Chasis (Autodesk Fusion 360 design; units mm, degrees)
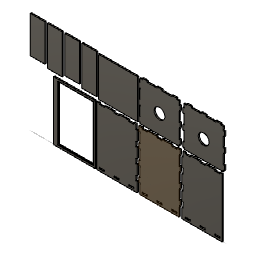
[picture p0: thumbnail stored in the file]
sketch "Sketch1" plane through (0, 0, 0) normal (0, 0, 1) x axis (1, 0, 0)
  line L1 (70, 421.7517) -> (-330, 421.7517)
  line L2 (508.2728, 1021.7517) -> (96.2728, 1021.7517)
  line L3 (508.2728, 421.7517) -> (508.2728, 1021.7517)
  line L4 (96.2728, 421.7517) -> (508.2728, 421.7517)
  line L5 (70, 971.7517) -> (82, 971.7517)
  line L6 (82, 871.7517) -> (70, 871.7517)
  line L7 (70, 821.7517) -> (82, 821.7517)
  line L8 (82, 721.7517) -> (70, 721.7517)
  line L9 (70, 671.7517) -> (82, 671.7517)
  line L10 (82, 571.7517) -> (70, 571.7517)
  line L11 (70, 521.7517) -> (82, 521.7517)
  line L12 (96.2728, 1021.7517) -> (108.2728, 1021.7517)
  line L13 (96.2728, 971.7517) -> (96.2728, 1021.7517)
  line L14 (108.2728, 971.7517) -> (96.2728, 971.7517)
  line L15 (108.2728, 1021.7517) -> (108.2728, 971.7517)
  line L16 (108.2728, 871.7517) -> (108.2728, 821.7517)
  line L17 (108.2728, 821.7517) -> (96.2728, 821.7517)
  line L18 (96.2728, 871.7517) -> (108.2728, 871.7517)
  line L19 (108.2728, 721.7517) -> (108.2728, 671.7517)
  line L20 (108.2728, 671.7517) -> (96.2728, 671.7517)
  line L21 (96.2728, 721.7517) -> (108.2728, 721.7517)
  line L22 (108.2728, 571.7517) -> (108.2728, 521.7517)
  line L23 (108.2728, 521.7517) -> (96.2728, 521.7517)
  line L24 (96.2728, 571.7517) -> (108.2728, 571.7517)
  line L25 (-342, 821.7517) -> (-330, 821.7517)
  line L26 (-342, 521.7517) -> (-330, 521.7517)
  line L27 (-330, 571.7517) -> (-342, 571.7517)
  line L28 (-342, 671.7517) -> (-330, 671.7517)
  line L29 (-330, 721.7517) -> (-342, 721.7517)
  line L30 (-330, 871.7517) -> (-342, 871.7517)
  line L31 (-330, 871.7517) -> (-330, 971.7517)
  line L32 (-330, 721.7517) -> (-330, 821.7517)
  line L33 (-330, 571.7517) -> (-330, 671.7517)
  line L34 (-330, 421.7517) -> (-330, 521.7517)
  line L35 (70, 521.7517) -> (70, 421.7517)
  line L36 (70, 671.7517) -> (70, 571.7517)
  line L37 (70, 821.7517) -> (70, 721.7517)
  line L38 (70, 971.7517) -> (70, 871.7517)
  line L39 (96.2728, 1021.7517) -> (96.2728, 421.7517)
  line L40 (-155, 441.7517) -> (-105, 441.7517)
  line L41 (-155, 453.7517) -> (-155, 441.7517)
  line L42 (-105, 453.7517) -> (-155, 453.7517)
  line L43 (-105, 441.7517) -> (-105, 453.7517)
  line L44 (45, 441.7517) -> (45, 453.7517)
  line L45 (-5, 441.7517) -> (45, 441.7517)
  line L46 (45, 453.7517) -> (-5, 453.7517)
  line L47 (-5, 453.7517) -> (-5, 441.7517)
  line L48 (-255, 441.7517) -> (-255, 453.7517)
  line L49 (-305, 441.7517) -> (-255, 441.7517)
  line L50 (-255, 453.7517) -> (-305, 453.7517)
  line L51 (-305, 453.7517) -> (-305, 441.7517)
  line L52 (283.2728, 453.7517) -> (283.2728, 441.7517)
  line L53 (333.2728, 453.7517) -> (283.2728, 453.7517)
  line L54 (333.2728, 441.7517) -> (333.2728, 453.7517)
  line L55 (333.2728, 441.7517) -> (283.2728, 441.7517)
  line L56 (483.2728, 453.7517) -> (433.2728, 453.7517)
  line L57 (433.2728, 453.7517) -> (433.2728, 441.7517)
  line L58 (483.2728, 441.7517) -> (433.2728, 441.7517)
  line L59 (483.2728, 441.7517) -> (483.2728, 453.7517)
  line L60 (183.2728, 453.7517) -> (133.2728, 453.7517)
  line L61 (133.2728, 453.7517) -> (133.2728, 441.7517)
  line L62 (183.2728, 441.7517) -> (133.2728, 441.7517)
  line L63 (183.2728, 441.7517) -> (183.2728, 453.7517)
  line L64 (-342, 971.7517) -> (-330, 971.7517)
  line L65 (82, 1021.7517) -> (-342, 1021.7517)
  line L66 (-255, 1021.7517) -> (-305, 1021.7517)
  line L67 (-255, 1009.7517) -> (-255, 1021.7517)
  line L68 (-305, 1009.7517) -> (-255, 1009.7517)
  line L69 (-305, 1021.7517) -> (-305, 1009.7517)
  line L70 (-105, 1021.7517) -> (-155, 1021.7517)
  line L71 (-105, 1009.7517) -> (-105, 1021.7517)
  line L72 (-155, 1009.7517) -> (-105, 1009.7517)
  line L73 (-155, 1021.7517) -> (-155, 1009.7517)
  line L74 (45, 1021.7517) -> (-5, 1021.7517)
  line L75 (45, 1009.7517) -> (45, 1021.7517)
  line L76 (-5, 1009.7517) -> (45, 1009.7517)
  line L77 (-5, 1021.7517) -> (-5, 1009.7517)
  line L78 (183.2728, 1021.7517) -> (133.2728, 1021.7517)
  line L79 (183.2728, 1009.7517) -> (183.2728, 1021.7517)
  line L80 (133.2728, 1009.7517) -> (183.2728, 1009.7517)
  line L81 (133.2728, 1021.7517) -> (133.2728, 1009.7517)
  line L82 (333.2728, 1021.7517) -> (283.2728, 1021.7517)
  line L83 (333.2728, 1009.7517) -> (333.2728, 1021.7517)
  line L84 (283.2728, 1009.7517) -> (333.2728, 1009.7517)
  line L85 (283.2728, 1021.7517) -> (283.2728, 1009.7517)
  line L86 (483.2728, 1021.7517) -> (433.2728, 1021.7517)
  line L87 (483.2728, 1009.7517) -> (483.2728, 1021.7517)
  line L88 (433.2728, 1009.7517) -> (483.2728, 1009.7517)
  line L89 (433.2728, 1021.7517) -> (433.2728, 1009.7517)
  line L90 (-353.2483, 1448.6304) -> (-751.2483, 1448.6304)
  line L91 (-353.2483, 1050.6304) -> (-353.2483, 1448.6304)
  line L92 (-751.2483, 1050.6304) -> (-353.2483, 1050.6304)
  line L93 (-751.2483, 1448.6304) -> (-751.2483, 1050.6304)
  line L94 (1883.2395, 210.7799) -> (1883.2395, -189.2201)
  line L95 (2283.2395, -189.2201) -> (2283.2395, 210.7799)
  line L96 (2283.2395, 210.7799) -> (1883.2395, 210.7799)
  line L97 (1883.2395, -189.2201) -> (2283.2395, -189.2201)
  line L98 (-342, 521.7517) -> (-342, 571.7517)
  line L99 (-342, 671.7517) -> (-342, 721.7517)
  line L100 (-342, 971.7517) -> (-342, 1021.7517)
  line L101 (-342, 821.7517) -> (-342, 871.7517)
  line L102 (82, 521.7517) -> (82, 571.7517)
  line L103 (82, 671.7517) -> (82, 721.7517)
  line L104 (82, 971.7517) -> (82, 1021.7517)
  line L105 (82, 821.7517) -> (82, 871.7517)
  line L106 (-305, 1459) -> (-255, 1459)
  line L107 (70, 1060) -> (82, 1060)
  line L108 (70, 1260) -> (70, 1360)
  line L109 (82, 1210) -> (82, 1260)
  line L110 (70, 1110) -> (70, 1210)
  line L111 (-330, 1210) -> (-342, 1210)
  line L112 (82, 1060) -> (82, 1110)
  line L113 (-330, 1210) -> (-330, 1110)
  line L114 (82, 1110) -> (70, 1110)
  line L115 (-330, 1060) -> (-342, 1060)
  line L116 (-330, 1360) -> (-330, 1260)
  line L117 (-342, 1210) -> (-342, 1260)
  line L118 (-330, 1060) -> (-330, 1047)
  line L119 (70, 1047) -> (70, 1060)
  line L120 (-330, 1047) -> (70, 1047)
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  point P55 (-305, 1021.7517)
  point P59 (-155, 1021.7517)
  point P63 (-5, 1021.7517)
  point P67 (133.2728, 1021.7517)
  point P71 (283.2728, 1021.7517)
  point P75 (433.2728, 1021.7517)
  point P39 (-305, 453.7517)
  point P79 (-305, 453.7517)
  point P24 (-330, 521.7517)
  point P80 (-330, 521.7517)
  point P23 (-330, 571.7517)
  point P81 (-330, 571.7517)
  point P26 (-330, 671.7517)
  point P82 (-330, 671.7517)
  point P42 (-255, 453.7517)
  point P83 (-255, 453.7517)
  point P41 (-305, 441.7517)
  point P84 (-305, 441.7517)
  point P40 (-255, 441.7517)
  point P85 (-255, 441.7517)
  point P32 (-155, 441.7517)
  point P86 (-155, 441.7517)
  point P33 (-155, 453.7517)
  point P87 (-155, 453.7517)
  point P34 (-105, 453.7517)
  point P88 (-105, 453.7517)
  point P31 (-105, 441.7517)
  point P89 (-105, 441.7517)
  point P35 (-5, 453.7517)
  point P90 (-5, 453.7517)
  point P38 (45, 453.7517)
  point P91 (45, 453.7517)
  point P36 (45, 441.7517)
  point P92 (45, 441.7517)
  point P37 (-5, 441.7517)
  point P93 (-5, 441.7517)
  point P12 (70, 521.7517)
  point P94 (70, 521.7517)
  point P13 (70, 571.7517)
  point P95 (70, 571.7517)
  point P10 (70, 671.7517)
  point P96 (70, 671.7517)
  point P27 (-330, 721.7517)
  point P97 (-330, 721.7517)
  point P11 (70, 721.7517)
  point P98 (70, 721.7517)
  point P8 (70, 821.7517)
  point P99 (70, 821.7517)
  point P9 (70, 871.7517)
  point P100 (70, 871.7517)
  point P25 (-330, 871.7517)
  point P101 (-330, 871.7517)
  point P29 (-330, 821.7517)
  point P102 (-330, 821.7517)
  point P28 (-330, 971.7517)
  point P103 (-330, 971.7517)
  point P58 (-305, 1009.7517)
  point P104 (-305, 1009.7517)
  point P57 (-255, 1009.7517)
  point P105 (-255, 1009.7517)
  point P62 (-155, 1009.7517)
  point P106 (-155, 1009.7517)
  point P61 (-105, 1009.7517)
  point P107 (-105, 1009.7517)
  point P66 (-5, 1009.7517)
  point P108 (-5, 1009.7517)
  point P65 (45, 1009.7517)
  point P109 (45, 1009.7517)
  point P7 (70, 971.7517)
  point P110 (70, 971.7517)
  point P70 (133.2728, 1009.7517)
  point P111 (133.2728, 1009.7517)
  point P69 (183.2728, 1009.7517)
  point P112 (183.2728, 1009.7517)
  point P74 (283.2728, 1009.7517)
  point P113 (283.2728, 1009.7517)
  point P73 (333.2728, 1009.7517)
  point P114 (333.2728, 1009.7517)
  point P78 (433.2728, 1009.7517)
  point P115 (433.2728, 1009.7517)
  point P77 (483.2728, 1009.7517)
  point P116 (483.2728, 1009.7517)
  point P16 (108.2728, 971.7517)
  point P117 (108.2728, 971.7517)
  point P18 (108.2728, 871.7517)
  point P118 (108.2728, 871.7517)
  point P17 (108.2728, 821.7517)
  point P119 (108.2728, 821.7517)
  point P20 (108.2728, 721.7517)
  point P120 (108.2728, 721.7517)
  point P19 (108.2728, 671.7517)
  point P121 (108.2728, 671.7517)
  point P22 (108.2728, 571.7517)
  point P122 (108.2728, 571.7517)
  point P21 (108.2728, 521.7517)
  point P123 (108.2728, 521.7517)
  point P52 (133.2728, 453.7517)
  point P124 (133.2728, 453.7517)
  point P53 (133.2728, 441.7517)
  point P125 (133.2728, 441.7517)
  point P51 (183.2728, 441.7517)
  point P126 (183.2728, 441.7517)
  point P54 (183.2728, 453.7517)
  point P127 (183.2728, 453.7517)
  point P45 (283.2728, 453.7517)
  point P128 (283.2728, 453.7517)
  point P44 (283.2728, 441.7517)
  point P129 (283.2728, 441.7517)
  point P43 (333.2728, 441.7517)
  point P130 (333.2728, 441.7517)
  point P46 (333.2728, 453.7517)
  point P131 (333.2728, 453.7517)
  point P48 (433.2728, 453.7517)
  point P132 (433.2728, 453.7517)
  point P50 (483.2728, 453.7517)
  point P133 (483.2728, 453.7517)
  point P47 (483.2728, 441.7517)
  point P134 (483.2728, 441.7517)
  point P49 (433.2728, 441.7517)
  point P135 (433.2728, 441.7517)
  point P569 (-342, 571.7517)
  point P571 (-342, 721.7517)
  point P573 (-342, 871.7517)
  point P577 (82, 571.7517)
  point P579 (82, 721.7517)
  point P581 (82, 871.7517)
  point P583 (96.2728, 871.7517)
  point P584 (96.2728, 821.7517)
  point P585 (96.2728, 721.7517)
  point P586 (96.2728, 671.7517)
  point P587 (96.2728, 571.7517)
  point P588 (96.2728, 521.7517)
  point P611 (-330, 1260)
  point P604 (-305, 1447)
  point P629 (-305, 1447)
  point P616 (-330, 1410)
  point P630 (-330, 1410)
  point P608 (-330, 1360)
  point P631 (-330, 1360)
  point P632 (-330, 1260)
  point P624 (-330, 1210)
  point P633 (-330, 1210)
  point P619 (-330, 1110)
  point P636 (-330, 1110)
  point P610 (70, 1110)
  point P642 (70, 1110)
  point P609 (70, 1210)
  point P635 (70, 1210)
  point P601 (70, 1260)
  point P639 (70, 1260)
  point P621 (70, 1360)
  point P644 (70, 1360)
  point P620 (70, 1410)
  point P641 (70, 1410)
  point P597 (45, 1447)
  point P637 (45, 1447)
  point P598 (-5, 1447)
  point P638 (-5, 1447)
  point P600 (-105, 1447)
  point P634 (-105, 1447)
  point P593 (-155, 1447)
  point P645 (-155, 1447)
  point P607 (-255, 1447)
  point P640 (-255, 1447)
  point P628 (-330, 1060)
  point P643 (-330, 1060)
  point P622 (70, 1060)
  point P646 (70, 1060)
  point P915 (145, 1447)
  point P919 (145, 1447)
  point P881 (120, 1410)
  point P899 (120, 1410)
  point P906 (120, 1360)
  point P910 (120, 1360)
  point P916 (120, 1260)
  point P932 (120, 1260)
  point P883 (120, 1210)
  point P933 (120, 1210)
  point P890 (120, 1110)
  point P922 (120, 1110)
  point P912 (520, 1110)
  point P930 (520, 1110)
  point P887 (520, 1210)
  point P909 (520, 1210)
  point P891 (520, 1260)
  point P914 (520, 1260)
  point P889 (520, 1360)
  point P935 (520, 1360)
  point P901 (520, 1410)
  point P907 (520, 1410)
  point P911 (495, 1447)
  point P913 (495, 1447)
  point P900 (445, 1447)
  point P934 (445, 1447)
  point P893 (345, 1447)
  point P903 (345, 1447)
  point P926 (295, 1447)
  point P936 (295, 1447)
  point P885 (195, 1447)
  point P894 (195, 1447)
  point P882 (120, 1060)
  point P918 (120, 1060)
  point P895 (520, 1060)
  point P937 (520, 1060)
  point P2 (-330, 421.7517)
  point P3 (70, 421.7517)
  point P6 (108.2728, 1021.7517)
  point P14 (96.2728, 1021.7517)
  point P56 (-255, 1021.7517)
  point P60 (-105, 1021.7517)
  point P64 (45, 1021.7517)
  point P68 (183.2728, 1021.7517)
  point P72 (333.2728, 1021.7517)
  point P76 (483.2728, 1021.7517)
  point P190 (-751.2483, 1448.6304)
  point P191 (-353.2483, 1448.6304)
  point P193 (-751.2483, 1050.6304)
  point P194 (2283.2395, 210.7799)
  point P196 (1883.2395, 210.7799)
  point P197 (1883.2395, -189.2201)
  point P591 (-330, 1447)
  point P592 (70, 1447)
  point P590 (-330, 1047)
  point P594 (-155, 1459)
  point P599 (-5, 1459)
  point P595 (-305, 1459)
  point P603 (82, 1260)
  point P618 (82, 1410)
  point P614 (82, 1110)
  point P613 (-342, 1260)
  point P617 (-342, 1410)
  point P627 (-342, 1110)
  point P897 (520, 1447)
  point P904 (120, 1447)
  point P921 (120, 1047)
  point P929 (295, 1459)
  point P884 (445, 1459)
  point P927 (145, 1459)
  point P902 (532, 1260)
  point P892 (532, 1410)
  point P886 (532, 1110)
  point P898 (108, 1260)
  point P931 (108, 1410)
  point P908 (108, 1110)
  point P946 (-1095.7754, 1461.2586)
  point P947 (-945.7754, 1461.2586)
  point P949 (-1095.7754, 1087.2586)
  point P950 (-921.6687, 1461.2586)
  point P951 (-771.6687, 1461.2586)
  point P953 (-921.6687, 1063.2586)
  point P954 (-1295.7754, 1461.2586)
  point P960 (-1445.7754, 1461.2586)
  point P957 (-1445.7754, 1087.2586)
  point P959 (-1271.6687, 1461.2586)
  point P961 (-1121.6687, 1461.2586)
  point P955 (-1271.6687, 1063.2586)
  point P962 (-785.4121, 1021.7517)
  point P963 (-1209.4121, 1021.7517)
  point P965 (-785.4121, 421.7517)
  horizontal L1
  vertical L35
  vertical L31
  horizontal L2
  vertical L3
  horizontal L4
  horizontal L5
  horizontal L6
  horizontal L7
  horizontal L8
  horizontal L9
  horizontal L10
  horizontal L11
  horizontal L12
  vertical L13
  horizontal L14
  vertical L15
  horizontal L18
  horizontal L17
  vertical L16
  horizontal L21
  horizontal L20
  vertical L19
  horizontal L24
  horizontal L23
  vertical L22
  horizontal L30
  horizontal L25
  horizontal L29
  horizontal L28
  horizontal L27
  horizontal L26
  collinear L31 L32
  collinear L32 L33
  collinear L33 L34
  collinear L35 L36
  collinear L36 L37
  collinear L37 L38
  perpendicular L12 L39
  horizontal L40
  vertical L41
  horizontal L42
  vertical L43
  horizontal L45
  vertical L47
  horizontal L46
  vertical L44
  horizontal L49
  vertical L51
  horizontal L50
  vertical L48
  vertical L52
  horizontal L53
  vertical L54
  perpendicular L54 L55
  vertical L57
  horizontal L56
  vertical L59
  perpendicular L58 L59
  vertical L61
  horizontal L60
  vertical L63
  perpendicular L62 L63
  horizontal L66
  vertical L67
  horizontal L68
  vertical L69
  coincident L65 P55
  horizontal L70
  vertical L71
  horizontal L72
  vertical L73
  coincident L65 P59
  horizontal L74
  vertical L75
  horizontal L76
  vertical L77
  coincident L65 P63
  horizontal L78
  vertical L79
  horizontal L80
  vertical L81
  coincident L2 P67
  horizontal L82
  vertical L83
  horizontal L84
  vertical L85
  coincident L2 P71
  horizontal L86
  vertical L87
  horizontal L88
  vertical L89
  coincident L2 P75
  coincident P39 P79
  coincident P24 P80
  coincident P23 P81
  coincident P26 P82
  coincident P42 P83
  coincident P41 P84
  coincident P40 P85
  coincident P32 P86
  coincident P33 P87
  coincident P34 P88
  coincident P31 P89
  coincident P35 P90
  coincident P38 P91
  coincident P36 P92
  coincident P37 P93
  coincident P12 P94
  coincident P13 P95
  coincident P10 P96
  coincident P27 P97
  coincident P11 P98
  coincident P8 P99
  coincident P9 P100
  coincident P25 P101
  coincident P29 P102
  coincident P28 P103
  coincident P58 P104
  coincident P57 P105
  coincident P62 P106
  coincident P61 P107
  coincident P66 P108
  coincident P65 P109
  coincident P7 P110
  coincident P70 P111
  coincident P69 P112
  coincident P74 P113
  coincident P73 P114
  coincident P78 P115
  coincident P77 P116
  coincident P16 P117
  coincident P18 P118
  coincident P17 P119
  coincident P20 P120
  coincident P19 P121
  coincident P22 P122
  coincident P21 P123
  coincident P52 P124
  coincident P53 P125
  coincident P51 P126
  coincident P54 P127
  coincident P45 P128
  coincident P44 P129
  coincident P43 P130
  coincident P46 P131
  coincident P48 P132
  coincident P50 P133
  coincident P47 P134
  coincident P49 P135
  horizontal L90
  vertical L91
  horizontal L92
  vertical L93
  horizontal L96
  vertical L95
  horizontal L97
  vertical L94
  perpendicular L1 L100
  coincident P569 L100
  collinear L98 L100
  coincident P571 L100
  collinear L99 L100
  coincident P573 L100
  collinear L100 L101
  perpendicular L1 L104
  coincident P577 L104
  collinear L102 L104
  coincident P579 L104
  collinear L103 L104
  coincident P581 L104
  collinear L104 L105
  coincident L39 P583
  coincident L39 P584
  coincident L39 P585
  coincident L39 P586
  coincident L39 P587
  coincident L39 P588
  horizontal L120
  vertical L118
  horizontal L106
  vertical L109
  horizontal L114
  vertical L112
  horizontal L107
  vertical L117
  horizontal L111
  coincident P611 L118
  horizontal L115
  collinear L116 L118
  collinear L113 L118
  coincident P604 P629
  coincident P616 P630
  coincident P608 P631
  coincident P611 P632
  coincident P624 P633
  coincident P619 P636
  coincident P610 P642
  coincident P609 P635
  coincident P601 P639
  coincident P621 P644
  coincident P620 P641
  coincident P597 P637
  coincident P598 P638
  coincident P600 P634
  coincident P593 P645
  coincident P607 P640
  coincident P628 P643
  coincident P622 P646
  coincident P915 P919
  coincident P881 P899
  coincident P906 P910
  coincident P916 P932
  coincident P883 P933
  coincident P890 P922
  coincident P912 P930
  coincident P887 P909
  coincident P891 P914
  coincident P889 P935
  coincident P901 P907
  coincident P911 P913
  coincident P900 P934
  coincident P893 P903
  coincident P926 P936
  coincident P885 P894
  coincident P882 P918
  coincident P895 P937
  dimension "d3" distance P2 P3 = 400
  dimension "d6" distance L2 L4 = 600
  dimension "d12" distance P8 P9 = 50
  dimension "d14" distance P10 P11 = 50
  dimension "d16" distance P12 P13 = 50
  dimension "d20" distance P6 P16 = 50
  dimension "d21" distance P6 P14 = 12
  dimension "d22" distance P17 P18 = 50
  dimension "d24" distance P19 P20 = 50
  dimension "d26" distance P21 P22 = 50
  dimension "d58" distance P31 P32 = 50
  dimension "d59" distance P31 P34 = 12
  dimension "d60" distance P36 P37 = 50
  dimension "d61" distance P36 P38 = 12
  dimension "d62" distance L43 L47 = 100
  dimension "d63" distance P40 P41 = 50
  dimension "d64" distance P40 P42 = 12
  dimension "d65" distance L41 L48 = 100
  dimension "d77" distance P43 P44 = 50
  dimension "d78" distance P43 P46 = 12
  dimension "d79" distance P47 P49 = 50
  dimension "d80" distance P47 P50 = 12
  dimension "d81" distance P51 P53 = 50
  dimension "d82" distance P51 P54 = 12
  dimension "d96" distance P55 P56 = 50
  dimension "d97" distance P55 P58 = 12
  dimension "d98" distance P59 P60 = 50
  dimension "d99" distance P59 P62 = 12
  dimension "d100" distance P63 P64 = 50
  dimension "d101" distance P63 P66 = 12
  dimension "d102" distance P67 P68 = 50
  dimension "d103" distance P67 P70 = 12
  dimension "d104" distance P71 P72 = 50
  dimension "d105" distance P71 P74 = 12
  dimension "d106" distance P75 P78 = 12
  dimension "d107" distance P75 P76 = 50
  dimension "d133" distance P190 P191 = 398
  dimension "d134" distance P190 P193 = 398
  dimension "d143" distance P194 P196 = 400
  dimension "d144" distance P196 P197 = 400
  dimension "d150" distance P591 P592 = 400
  dimension "d151" distance P590 P591 = 400
  dimension "d152" distance P593 P594 = 12
  dimension "d153" distance P597 P598 = 50
  dimension "d154" distance P598 P599 = 12
  dimension "d155" distance P604 P607 = 50
  dimension "d156" distance P595 P604 = 12
  dimension "d157" distance P601 P603 = 12
  dimension "d158" distance P601 P609 = 50
  dimension "d159" distance P618 P620 = 12
  dimension "d160" distance P620 P621 = 50
  dimension "d161" distance P610 P614 = 12
  dimension "d162" distance P610 P622 = 50
  dimension "d163" distance P611 P624 = 50
  dimension "d164" distance P611 P613 = 12
  dimension "d165" distance P608 P616 = 50
  dimension "d166" distance P616 P617 = 12
  dimension "d167" distance P619 P628 = 50
  dimension "d168" distance P619 P627 = 12
  dimension "d171" diameter = 6.4
  dimension "d172" diameter = 6.4
  dimension "d173" diameter = 6.4
  dimension "d174" diameter = 6.4
  dimension "d175" diameter = 6.4
  dimension "d176" diameter = 6.4
  dimension "d177" diameter = 6.4
  dimension "d178" diameter = 6.4
  dimension "d179" diameter = 6.4
  dimension "d180" diameter = 6.4
  dimension "d181" diameter = 6.4
  dimension "d182" diameter = 6.4
  dimension "d183" diameter = 6.4
  dimension "d184" diameter = 6.4
  dimension "d185" diameter = 6.4
  dimension "d186" diameter = 6.4
  dimension "d187" diameter = 6.4
  dimension "d188" diameter = 6.4
  dimension "d189" diameter = 6.4
  dimension "d190" diameter = 6.4
  dimension "d191" diameter = 6.4
  dimension "d192" diameter = 6.4
  dimension "d193" diameter = 6.4
  dimension "d194" diameter = 6.4
  dimension "d195" diameter = 6.4
  dimension "d196" diameter = 6.4
  dimension "d197" diameter = 6.4
  dimension "d198" diameter = 6.4
  dimension "d199" diameter = 6.4
  dimension "d200" diameter = 6.4
  dimension "d201" diameter = 6.4
  dimension "d202" diameter = 6.4
  dimension "d203" diameter = 6.4
  dimension "d204" diameter = 6.4
  dimension "d205" diameter = 6.4
  dimension "d206" diameter = 6.4
  dimension "d207" diameter = 6.4
  dimension "d208" diameter = 6.4
  dimension "d209" diameter = 6.4
  dimension "d210" diameter = 6.4
  dimension "d211" diameter = 6.4
  dimension "d212" diameter = 6.4
  dimension "d213" diameter = 6.4
  dimension "d214" diameter = 6.4
  dimension "d215" diameter = 6.4
  dimension "d216" diameter = 6.4
  dimension "d217" diameter = 6.4
  dimension "d218" diameter = 6.4
  dimension "d219" diameter = 6.4
  dimension "d220" diameter = 6.4
  dimension "d221" diameter = 6.4
  dimension "d222" diameter = 6.4
  dimension "d223" diameter = 6.4
  dimension "d224" diameter = 6.4
  dimension "d225" diameter = 6.4
  dimension "d226" diameter = 6.4
  dimension "d227" diameter = 6.4
  dimension "d228" diameter = 6.4
  dimension "d230" distance L3 L39 = 412
  dimension "d231" diameter = 6.4
  dimension "d232" diameter = 6.4
  dimension "d233" diameter = 6.4
  dimension "d234" diameter = 6.4
  dimension "d235" diameter = 6.4
  dimension "d236" diameter = 6.4
  dimension "d237" diameter = 6.4
  dimension "d238" diameter = 6.4
  dimension "d239" diameter = 6.4
  dimension "d240" diameter = 6.4
  dimension "d241" diameter = 6.4
  dimension "d242" diameter = 6.4
  dimension "d243" diameter = 6.4
  dimension "d244" diameter = 6.4
  dimension "d245" diameter = 6.4
  dimension "d246" diameter = 6.4
  dimension "d247" diameter = 6.4
  dimension "d248" diameter = 6.4
  dimension "d249" distance P897 P904 = 400
  dimension "d250" distance P904 P921 = 400
  dimension "d251" distance P926 P929 = 12
  dimension "d252" distance P900 P913 = 50
  dimension "d253" distance P884 P900 = 12
  dimension "d254" distance P885 P915 = 50
  dimension "d255" distance P915 P927 = 12
  dimension "d256" distance P902 P914 = 12
  dimension "d257" distance P887 P914 = 50
  dimension "d258" distance P892 P907 = 12
  dimension "d259" distance P889 P907 = 50
  dimension "d260" distance P886 P930 = 12
  dimension "d261" distance P895 P930 = 50
  dimension "d262" distance P883 P916 = 50
  dimension "d263" distance P898 P916 = 12
  dimension "d264" distance P881 P906 = 50
  dimension "d265" distance P881 P931 = 12
  dimension "d266" distance P882 P922 = 50
  dimension "d267" distance P908 P922 = 12
  dimension "d268" diameter = 6.4
  dimension "d269" diameter = 6.4
  dimension "d270" diameter = 6.4
  dimension "d271" diameter = 6.4
  dimension "d272" diameter = 6.4
  dimension "d273" diameter = 6.4
  dimension "d274" diameter = 6.4
  dimension "d275" diameter = 6.4
  dimension "d276" diameter = 6.4
  dimension "d277" diameter = 6.4
  dimension "d278" diameter = 6.4
  dimension "d279" diameter = 6.4
  dimension "d280" diameter = 6.4
  dimension "d281" diameter = 6.4
  dimension "d282" diameter = 6.4
  dimension "d283" diameter = 6.4
  dimension "d284" diameter = 6.4
  dimension "d285" diameter = 6.4
  dimension "d288" distance P946 P947 = 150
  dimension "d289" distance P946 P949 = 374
  dimension "d290" distance P950 P951 = 150
  dimension "d291" distance P950 P953 = 398
  dimension "d296" distance P954 P960 = 150
  dimension "d297" distance P957 P960 = 374
  dimension "d298" distance P959 P961 = 150
  dimension "d299" distance P955 P959 = 398
  dimension "d300" distance P962 P963 = 424
  dimension "d301" distance P962 P965 = 600
extrude "Extrude7" new body sketch "Sketch1" along normal blind 12
sketch "Sketch4" plane through (0, 0, 12) normal (0, 0, 1) x axis (1, 0, 0)
  line L1 (-1159.4121, 996.7517) -> (-1159.4121, 446.7517)
  line L2 (-810.4121, 996.7517) -> (-1159.4121, 996.7517)
  line L3 (-810.4121, 446.7517) -> (-810.4121, 996.7517)
  line L4 (-1159.4121, 446.7517) -> (-810.4121, 446.7517)
  line L5 (-785.4121, 1021.7517) -> (-785.4121, 421.7517)
  line L6 (-1209.4121, 1021.7517) -> (-785.4121, 1021.7517)
  line L7 (-1209.4121, 421.7517) -> (-1209.4121, 1021.7517)
  line L8 (-785.4121, 421.7517) -> (-1209.4121, 421.7517)
  line L9 (-803.4121, 439.7517) -> (-803.4121, 1003.7517)
  line L10 (-1166.4121, 439.7517) -> (-803.4121, 439.7517)
  line L11 (-1166.4121, 1003.7517) -> (-1166.4121, 439.7517)
  line L12 (-803.4121, 1003.7517) -> (-1166.4121, 1003.7517)
  circle C1 centre (-1166.4121, 1000.5517) radius 3.2
  circle C2 centre (-803.3148, 1000.5531) radius 3.2
  circle C3 centre (-1166.4121, 442.9517) radius 3.2
  circle C4 centre (-803.4121, 442.9517) radius 3.2
  point P13 (-1166.4121, 1003.7517)
  point P10 (-803.4121, 1003.7517)
  point P12 (-1166.4121, 439.7517)
  point P11 (-803.4121, 439.7517)
  coincident P13 C1
  coincident P10 C2
  coincident P12 C3
  coincident P11 C4
  dimension "d306" = -7
  dimension "d307" diameter C1 = 6.4
  dimension "d308" diameter C2 = 6.4
  dimension "d309" diameter C3 = 6.4
  dimension "d310" diameter C4 = 6.4
extrude "Extrude8" cut sketch "Sketch4" profile of L1 L2 L3 L4 L9 L10 L12 L11 C1 C2 C3 C4 against normal blind 5
sketch "Sketch5" plane through (0, 0, 12) normal (0, 0, 1) x axis (1, 0, 0)
  line L1 (-105, 441.7517) -> (-105, 453.7517)
  line L2 (-148.6, 441.7517) -> (-111.4, 441.7517)
  line L3 (-155, 453.7517) -> (-155, 441.7517)
  line L4 (-111.4, 453.7517) -> (-148.6, 453.7517)
  line L5 (-261.4, 453.7517) -> (-298.6, 453.7517)
  line L6 (-255, 441.7517) -> (-255, 453.7517)
  line L7 (-298.6, 441.7517) -> (-261.4, 441.7517)
  line L8 (-305, 453.7517) -> (-305, 441.7517)
  line L9 (38.6, 453.7517) -> (1.4, 453.7517)
  line L10 (45, 441.7517) -> (45, 453.7517)
  line L11 (1.4, 441.7517) -> (38.6, 441.7517)
  line L12 (-5, 453.7517) -> (-5, 441.7517)
  line L13 (70, 571.7517) -> (82, 571.7517)
  line L14 (70, 665.3517) -> (70, 578.1517)
  line L15 (82, 671.7517) -> (70, 671.7517)
  line L16 (82, 721.7517) -> (82, 671.7517)
  line L17 (70, 721.7517) -> (82, 721.7517)
  line L18 (70, 815.3517) -> (70, 728.1517)
  line L19 (82, 821.7517) -> (70, 821.7517)
  line L20 (82, 871.7517) -> (82, 821.7517)
  line L21 (70, 871.7517) -> (82, 871.7517)
  line L22 (70, 965.3517) -> (70, 878.1517)
  line L23 (82, 971.7517) -> (70, 971.7517)
  line L24 (82, 1021.7517) -> (82, 971.7517)
  line L25 (45, 1021.7517) -> (82, 1021.7517)
  line L26 (45, 1009.7517) -> (45, 1021.7517)
  line L27 (1.4, 1009.7517) -> (38.6, 1009.7517)
  line L28 (-5, 1021.7517) -> (-5, 1009.7517)
  line L29 (-105, 1021.7517) -> (-5, 1021.7517)
  line L30 (-105, 1009.7517) -> (-105, 1021.7517)
  line L31 (-148.6, 1009.7517) -> (-111.4, 1009.7517)
  line L32 (-155, 1021.7517) -> (-155, 1009.7517)
  line L33 (-255, 1021.7517) -> (-155, 1021.7517)
  line L34 (-255, 1009.7517) -> (-255, 1021.7517)
  line L35 (-298.6, 1009.7517) -> (-261.4, 1009.7517)
  line L36 (-305, 1021.7517) -> (-305, 1009.7517)
  line L37 (-342, 1021.7517) -> (-305, 1021.7517)
  line L38 (-342, 971.7517) -> (-342, 1021.7517)
  line L39 (-330, 971.7517) -> (-342, 971.7517)
  line L40 (-330, 878.1517) -> (-330, 965.3517)
  line L41 (-342, 871.7517) -> (-330, 871.7517)
  line L42 (-342, 821.7517) -> (-342, 871.7517)
  line L43 (-330, 821.7517) -> (-342, 821.7517)
  line L44 (-330, 728.1517) -> (-330, 815.3517)
  line L45 (-342, 721.7517) -> (-330, 721.7517)
  line L46 (-342, 671.7517) -> (-342, 721.7517)
  line L47 (-330, 671.7517) -> (-342, 671.7517)
  line L48 (-330, 578.1517) -> (-330, 665.3517)
  line L49 (-342, 571.7517) -> (-330, 571.7517)
  line L50 (-342, 521.7517) -> (-342, 571.7517)
  line L51 (-330.0793, 521.7517) -> (-342, 521.7517)
  line L52 (-330, 421.7517) -> (-330, 515.3521)
  line L53 (70, 421.7517) -> (-330, 421.7517)
  line L54 (70, 515.3517) -> (70, 421.7517)
  line L55 (82, 521.7517) -> (70, 521.7517)
  line L56 (82, 571.7517) -> (82, 521.7517)
  arc A1 centre (-108.2, 453.7517) radius 3.2 clockwise from (-111.4, 453.7517) to (-105, 453.7517)
  arc A2 centre (-108.2, 441.7517) radius 3.2 clockwise from (-105, 441.7517) to (-111.4, 441.7517)
  arc A3 centre (-151.8, 441.7517) radius 3.2 clockwise from (-148.6, 441.7517) to (-155, 441.7517)
  arc A4 centre (-151.8, 453.7517) radius 3.2 clockwise from (-155, 453.7517) to (-148.6, 453.7517)
  arc A5 centre (-301.8, 453.7517) radius 3.2 clockwise from (-305, 453.7517) to (-298.6, 453.7517)
  arc A6 centre (-258.2, 453.7517) radius 3.2 clockwise from (-261.4, 453.7517) to (-255, 453.7517)
  arc A7 centre (-258.2, 441.7517) radius 3.2 clockwise from (-255, 441.7517) to (-261.4, 441.7517)
  arc A8 centre (-301.8, 441.7517) radius 3.2 clockwise from (-298.6, 441.7517) to (-305, 441.7517)
  arc A9 centre (-1.8, 453.7517) radius 3.2 clockwise from (-5, 453.7517) to (1.4, 453.7517)
  arc A10 centre (41.8, 453.7517) radius 3.2 clockwise from (38.6, 453.7517) to (45, 453.7517)
  arc A11 centre (41.8, 441.7517) radius 3.2 clockwise from (45, 441.7517) to (38.6, 441.7517)
  arc A12 centre (-1.8, 441.7517) radius 3.2 clockwise from (1.4, 441.7517) to (-5, 441.7517)
  arc A13 centre (70, 574.9517) radius 3.2 clockwise from (70, 571.7517) to (70, 578.1517)
  arc A14 centre (70, 668.5517) radius 3.2 clockwise from (70, 665.3517) to (70, 671.7517)
  arc A15 centre (70, 724.9517) radius 3.2 clockwise from (70, 721.7517) to (70, 728.1517)
  arc A16 centre (70, 818.5517) radius 3.2 clockwise from (70, 815.3517) to (70, 821.7517)
  arc A17 centre (70, 874.9517) radius 3.2 clockwise from (70, 871.7517) to (70, 878.1517)
  arc A18 centre (70, 968.5517) radius 3.2 clockwise from (70, 965.3517) to (70, 971.7517)
  arc A19 centre (41.8, 1009.7517) radius 3.2 clockwise from (45, 1009.7517) to (38.6, 1009.7517)
  arc A20 centre (-1.8, 1009.7517) radius 3.2 clockwise from (1.4, 1009.7517) to (-5, 1009.7517)
  arc A21 centre (-108.2, 1009.7517) radius 3.2 clockwise from (-105, 1009.7517) to (-111.4, 1009.7517)
  arc A22 centre (-151.8, 1009.7517) radius 3.2 clockwise from (-148.6, 1009.7517) to (-155, 1009.7517)
  arc A23 centre (-258.2, 1009.7517) radius 3.2 clockwise from (-255, 1009.7517) to (-261.4, 1009.7517)
  arc A24 centre (-301.8, 1009.7517) radius 3.2 clockwise from (-298.6, 1009.7517) to (-305, 1009.7517)
  arc A25 centre (-330, 968.5517) radius 3.2 clockwise from (-330, 971.7517) to (-330, 965.3517)
  arc A26 centre (-330, 874.9517) radius 3.2 clockwise from (-330, 878.1517) to (-330, 871.7517)
  arc A27 centre (-330, 818.5517) radius 3.2 clockwise from (-330, 821.7517) to (-330, 815.3517)
  arc A28 centre (-330, 724.9517) radius 3.2 clockwise from (-330, 728.1517) to (-330, 721.7517)
  arc A29 centre (-330, 668.5517) radius 3.2 clockwise from (-330, 671.7517) to (-330, 665.3517)
  arc A30 centre (-330, 574.9517) radius 3.2 clockwise from (-330, 578.1517) to (-330, 571.7517)
  arc A31 centre (-330.0396, 518.5519) radius 3.2 clockwise from (-330.0793, 521.7517) to (-330, 515.3521)
  arc A32 centre (70, 518.5517) radius 3.2 clockwise from (70, 515.3517) to (70, 521.7517)
sketch "Sketch6" plane through (0, 0, 12) normal (0, 0, 1) x axis (1, 0, 0)
  line L1 (-342, 1410) -> (-330, 1410)
  line L2 (-342, 1360) -> (-342, 1410)
  line L3 (-330, 1360) -> (-342, 1360)
  line L4 (-330, 1266.4) -> (-330, 1353.6)
  line L5 (-342, 1260) -> (-330, 1260)
  line L6 (-342, 1210) -> (-342, 1260)
  line L7 (-330, 1210) -> (-342, 1210)
  line L8 (-330, 1116.4) -> (-330, 1203.6)
  line L9 (-342, 1110) -> (-330, 1110)
  line L10 (-342, 1060) -> (-342, 1110)
  line L11 (-330, 1060) -> (-342, 1060)
  line L12 (-330, 1047) -> (-330, 1053.6)
  line L13 (70, 1047) -> (-330, 1047)
  line L14 (70, 1053.6054) -> (70, 1047)
  line L15 (82, 1060) -> (70, 1060)
  line L16 (82, 1110) -> (82, 1060)
  line L17 (70, 1110) -> (82, 1110)
  line L18 (70, 1203.6) -> (70, 1116.4)
  line L19 (82, 1210) -> (70, 1210)
  line L20 (82, 1260) -> (82, 1210)
  line L21 (70, 1260) -> (82, 1260)
  line L22 (70, 1353.6) -> (70, 1266.4)
  line L23 (82, 1360) -> (70, 1360)
  line L24 (82, 1410) -> (82, 1360)
  line L25 (70, 1410) -> (82, 1410)
  line L26 (70, 1447) -> (70, 1416.4)
  line L27 (51.4, 1447) -> (70, 1447)
  line L28 (45, 1459) -> (45, 1447)
  line L29 (-5, 1459) -> (45, 1459)
  line L30 (-5, 1447) -> (-5, 1459)
  line L31 (-98.6, 1447) -> (-11.4, 1447)
  line L32 (-105, 1459) -> (-105, 1447)
  line L33 (-155, 1459) -> (-105, 1459)
  line L34 (-155, 1447) -> (-155, 1459)
  line L35 (-248.6, 1447) -> (-161.4, 1447)
  line L36 (-255, 1459) -> (-255, 1447)
  line L37 (-305, 1459) -> (-255, 1459)
  line L38 (-305, 1447) -> (-305, 1459)
  line L39 (-330, 1447) -> (-311.4, 1447)
  line L40 (-330, 1416.4) -> (-330, 1447)
  arc A1 centre (-330, 1356.8) radius 3.2 clockwise from (-330, 1360) to (-330, 1353.6)
  arc A2 centre (-330, 1263.2) radius 3.2 clockwise from (-330, 1266.4) to (-330, 1260)
  arc A3 centre (-330, 1206.8) radius 3.2 clockwise from (-330, 1210) to (-330, 1203.6)
  arc A4 centre (-330, 1113.2) radius 3.2 clockwise from (-330, 1116.4) to (-330, 1110)
  arc A5 centre (-330, 1056.8) radius 3.2 clockwise from (-330, 1060) to (-330, 1053.6)
  arc A6 centre (69.8686, 1056.8027) radius 3.2 clockwise from (70, 1053.6054) to (70, 1060)
  arc A7 centre (70, 1113.2) radius 3.2 clockwise from (70, 1110) to (70, 1116.4)
  arc A8 centre (70, 1206.8) radius 3.2 clockwise from (70, 1203.6) to (70, 1210)
  arc A9 centre (70, 1263.2) radius 3.2 clockwise from (70, 1260) to (70, 1266.4)
  arc A10 centre (70, 1356.8) radius 3.2 clockwise from (70, 1353.6) to (70, 1360)
  arc A11 centre (70, 1413.2) radius 3.2 clockwise from (70, 1410) to (70, 1416.4)
  arc A12 centre (48.2, 1447) radius 3.2 clockwise from (51.4, 1447) to (45, 1447)
  arc A13 centre (-8.2, 1447) radius 3.2 clockwise from (-5, 1447) to (-11.4, 1447)
  arc A14 centre (-101.8, 1447) radius 3.2 clockwise from (-98.6, 1447) to (-105, 1447)
  arc A15 centre (-158.2, 1447) radius 3.2 clockwise from (-155, 1447) to (-161.4, 1447)
  arc A16 centre (-251.8, 1447) radius 3.2 clockwise from (-248.6, 1447) to (-255, 1447)
  arc A17 centre (-308.2, 1447) radius 3.2 clockwise from (-305, 1447) to (-311.4, 1447)
  arc A18 centre (-330, 1413.2) radius 3.2 clockwise from (-330, 1416.4) to (-330, 1410)
  circle C1 centre (-130, 1235) radius 55
  dimension "d313" diameter C1 = 110
extrude "Extrude9" cut sketch "Sketch6" profile of C1 against normal blind 100
sketch "Sketch7" plane through (0, 0, 12) normal (0, 0, 1) x axis (1, 0, 0)
  line L1 (108, 1410) -> (120, 1410)
  line L2 (108, 1360) -> (108, 1410)
  line L3 (120, 1360) -> (108, 1360)
  line L4 (120, 1266.4) -> (120, 1353.6)
  line L5 (108, 1260) -> (120, 1260)
  line L6 (108, 1210) -> (108, 1260)
  line L7 (120, 1210) -> (108, 1210)
  line L8 (120, 1116.4) -> (120, 1203.6)
  line L9 (108, 1110) -> (120, 1110)
  line L10 (108, 1060) -> (108, 1110)
  line L11 (120, 1060) -> (108, 1060)
  line L12 (120, 1047) -> (120, 1053.6)
  line L13 (520, 1047) -> (120, 1047)
  line L14 (520, 1053.6054) -> (520, 1047)
  line L15 (532, 1060) -> (520, 1060)
  line L16 (532, 1110) -> (532, 1060)
  line L17 (520, 1110) -> (532, 1110)
  line L18 (520, 1203.6) -> (520, 1116.4)
  line L19 (532, 1210) -> (520, 1210)
  line L20 (532, 1260) -> (532, 1210)
  line L21 (520, 1260) -> (532, 1260)
  line L22 (520, 1353.6) -> (520, 1266.4)
  line L23 (532, 1360) -> (520, 1360)
  line L24 (532, 1410) -> (532, 1360)
  line L25 (520, 1410) -> (532, 1410)
  line L26 (520, 1447) -> (520, 1416.4)
  line L27 (501.4, 1447) -> (520, 1447)
  line L28 (495, 1459) -> (495, 1447)
  line L29 (445, 1459) -> (495, 1459)
  line L30 (445, 1447) -> (445, 1459)
  line L31 (351.4, 1447) -> (438.6, 1447)
  line L32 (345, 1459) -> (345, 1447)
  line L33 (295, 1459) -> (345, 1459)
  line L34 (295, 1447) -> (295, 1459)
  line L35 (201.4, 1447) -> (288.6, 1447)
  line L36 (195, 1459) -> (195, 1447)
  line L37 (145, 1459) -> (195, 1459)
  line L38 (145, 1447) -> (145, 1459)
  line L39 (120, 1447) -> (138.6, 1447)
  line L40 (120, 1416.4) -> (120, 1447)
  arc A1 centre (120, 1356.8) radius 3.2 clockwise from (120, 1360) to (120, 1353.6)
  arc A2 centre (120, 1263.2) radius 3.2 clockwise from (120, 1266.4) to (120, 1260)
  arc A3 centre (120, 1206.8) radius 3.2 clockwise from (120, 1210) to (120, 1203.6)
  arc A4 centre (120, 1113.2) radius 3.2 clockwise from (120, 1116.4) to (120, 1110)
  arc A5 centre (120, 1056.8) radius 3.2 clockwise from (120, 1060) to (120, 1053.6)
  arc A6 centre (519.8686, 1056.8027) radius 3.2 clockwise from (520, 1053.6054) to (520, 1060)
  arc A7 centre (520, 1113.2) radius 3.2 clockwise from (520, 1110) to (520, 1116.4)
  arc A8 centre (520, 1206.8) radius 3.2 clockwise from (520, 1203.6) to (520, 1210)
  arc A9 centre (520, 1263.2) radius 3.2 clockwise from (520, 1260) to (520, 1266.4)
  arc A10 centre (520, 1356.8) radius 3.2 clockwise from (520, 1353.6) to (520, 1360)
  arc A11 centre (520, 1413.2) radius 3.2 clockwise from (520, 1410) to (520, 1416.4)
  arc A12 centre (498.2, 1447) radius 3.2 clockwise from (501.4, 1447) to (495, 1447)
  arc A13 centre (441.8, 1447) radius 3.2 clockwise from (445, 1447) to (438.6, 1447)
  arc A14 centre (348.2, 1447) radius 3.2 clockwise from (351.4, 1447) to (345, 1447)
  arc A15 centre (291.8, 1447) radius 3.2 clockwise from (295, 1447) to (288.6, 1447)
  arc A16 centre (198.2, 1447) radius 3.2 clockwise from (201.4, 1447) to (195, 1447)
  arc A17 centre (141.8, 1447) radius 3.2 clockwise from (145, 1447) to (138.6, 1447)
  arc A18 centre (120, 1413.2) radius 3.2 clockwise from (120, 1416.4) to (120, 1410)
  circle C1 centre (320, 1235) radius 55
  dimension "d316" diameter C1 = 110
extrude "Extrude10" cut sketch "Sketch7" profile of C1 against normal blind 100
sketch "Sketch2" plane through (0, 0, 0) normal (0, 0, 1) x axis (1, 0, 0)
